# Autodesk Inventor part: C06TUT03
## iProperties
Created: 2009-04
Part Number: C06TUT03
Document SubType Name: Modeling
Designer: Sham
Density: 1 g/cm^3
Author: Sham
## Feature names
1. Extrusion1
2. Extrusion2
3. Extrusion3
4. Hole1
5. Extrusion4
6. Circular Pattern1
7. Mirror1
